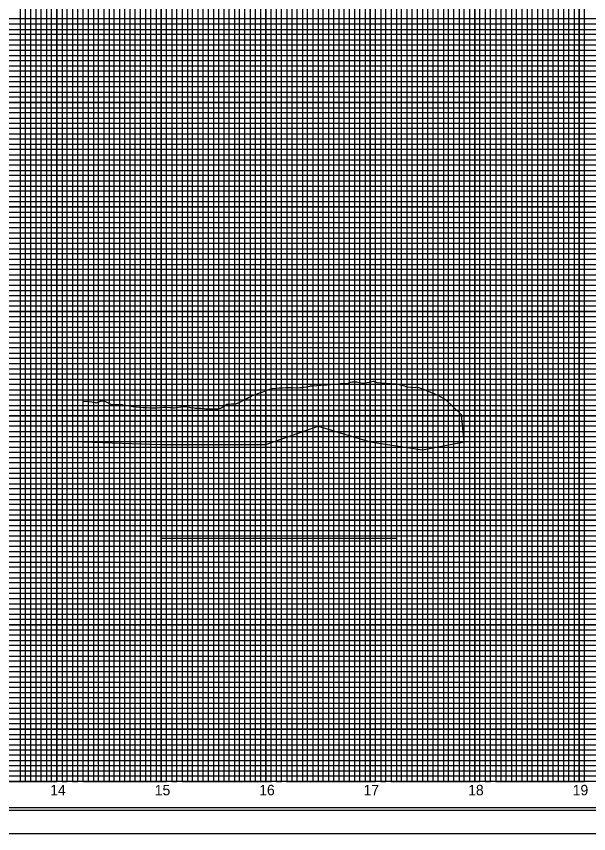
# Model space of a CAD drawing. Extents: x 1632447 to 1634147, y 883210 to 885181.
# Drawn here: x 1633075 to 1633623, y 883898 to 884680 of the extents above; entities that cross this region are included whole.
import ezdxf

# ---------------------------------------------------------------- set-up
doc = ezdxf.new("R2010")
doc.units = 0
for name, color, linetype in [('Exist Vertical Profile Horizontal Axis Label Major', 7, 'Continuous'), ('Prop CMT Undercut Boundary', 7, 'Continuous'), ('Prop VPI Label', 7, 'Continuous'), ('Scratch_Level_8', 7, 'Continuous'), ('Sheet Cutting Line CELL', 7, 'Continuous'), ('Sheet DOT Grid CELL', 7, 'Continuous'), ('Sheet Plot Border Inside CELL', 7, 'Continuous'), ('Sheet Plot Border Outside CELL', 7, 'Continuous'), ('Sheet Profile CELL', 7, 'Continuous'), ('Sheet Profile Grid Major CELL', 7, 'Continuous'), ('Sheet Profile Grid Middle CELL', 7, 'Continuous'), ('Sheet Profile Grid Minor CELL', 7, 'Continuous'), ('Stewart Plot Border Xerox6279 and LJ5000', 7, 'Continuous')]:
    doc.layers.add(name, color=color, linetype=linetype)

msp = doc.modelspace()

# ---------------------------------------------------------------- linework, layer by layer
at = {"layer": 'Prop CMT Undercut Boundary'}
for p, q in [((1633138.86, 884311.82), (1633138.86, 884272.61)), ((1633501.21, 884298.45), (1633485.73, 884313.21)), ((1633503.86, 884272.61), (1633501.21, 884298.45)), ((1633313.86, 884270.11), (1633363.86, 884287.61)), ((1633363.86, 884287.61), (1633413.86, 884272.61)), ((1633138.86, 884272.61), (1633213.86, 884270.11)), ((1633413.86, 884272.61), (1633463.86, 884265.11)), ((1633463.86, 884265.11), (1633503.86, 884272.61)), ((1633213.86, 884270.11), (1633313.86, 884270.11))]:
    msp.add_line(p, q, dxfattribs=at)
msp.add_lwpolyline([(1633138.86, 884311.82), (1633144.17, 884311.31), (1633147.43, 884310.96), (1633150.69, 884310.26), (1633151.68, 884310.05), (1633153.95, 884311.08), (1633156.17, 884312.08), (1633157.2, 884311.98), (1633159.45, 884311.77), (1633160.46, 884311.28), (1633163.72, 884309.68), (1633166.24, 884308.45), (1633166.98, 884308.44), (1633170.24, 884308.42), (1633173.5, 884308.39), (1633174.84, 884308.38), (1633176.31, 884308.37), (1633176.75, 884308.3), (1633180.01, 884307.76), (1633183.27, 884307.22), (1633186.53, 884306.71), (1633188.67, 884306.43), (1633189.79, 884306.33), (1633193.05, 884306.04), (1633196.41, 884305.74), (1633197.25, 884305.54), (1633199.56, 884305.51), (1633202.82, 884305.45), (1633206.08, 884305.4), (1633206.45, 884305.39), (1633208.29, 884305.36), (1633209.34, 884305.42), (1633212.6, 884305.64), (1633215.85, 884305.85), (1633216.49, 884305.89), (1633219.11, 884305.82), (1633222.37, 884305.72), (1633223.46, 884305.69), (1633225.63, 884305.35), (1633226.52, 884305.2), (1633228.89, 884305.63), (1633232.15, 884306.22), (1633232.82, 884306.35), (1633235.4, 884306.5), (1633236.54, 884306.56), (1633238.66, 884306.23), (1633240.77, 884305.9), (1633241.92, 884305.71), (1633245.18, 884305.15), (1633246.56, 884304.91), (1633248.44, 884304.9), (1633251.7, 884304.87), (1633254.95, 884304.58), (1633256.58, 884304.43), (1633258.21, 884304.43), (1633261.47, 884304.41), (1633261.94, 884304.41), (1633264.73, 884304.29), (1633266.59, 884304.22), (1633267.99, 884304.44), (1633270.85, 884304.9), (1633271.25, 884305.16), (1633274.5, 884307.32), (1633276.59, 884308.7), (1633277.76, 884308.81), (1633281.02, 884309.11), (1633281.97, 884309.19), (1633284.28, 884309.16), (1633285.04, 884309.15), (1633287.54, 884309.95), (1633287.92, 884310.07), (1633290.8, 884311.62), (1633294.05, 884313.36), (1633297.31, 884315.09), (1633300.19, 884316.53), (1633300.57, 884316.76), (1633300.99, 884317.01), (1633303.83, 884318.05), (1633307.09, 884319.25), (1633310.35, 884320.45), (1633313.6, 884321.64), (1633316.86, 884322.83), (1633320.12, 884323.94), (1633323.38, 884324.12), (1633326.64, 884324.3), (1633329.9, 884324.52), (1633333.15, 884324.63), (1633336.6, 884324.75), (1633339.67, 884324.64), (1633343.19, 884324.52), (1633346.19, 884324.78), (1633346.6, 884324.82), (1633349.45, 884324.92), (1633350.15, 884324.94), (1633352.7, 884325.49), (1633355.96, 884326.19), (1633356.61, 884326.33), (1633359.22, 884326.48), (1633362.75, 884326.68), (1633365.74, 884327.02), (1633366.61, 884327.13), (1633369, 884327.2), (1633372.43, 884327.32), (1633375.51, 884327.76), (1633376.62, 884327.92), (1633378.77, 884327.88), (1633382.04, 884327.83), (1633385.29, 884328.49), (1633386.63, 884328.76), (1633388.55, 884328.7), (1633391.8, 884328.69), (1633395.06, 884329.78), (1633396.64, 884330.31), (1633398.32, 884330.28), (1633401.08, 884330.23), (1633406.66, 884328.94), (1633412.9, 884329.75), (1633416.67, 884330.91), (1633420.04, 884329.7), (1633426.69, 884328.82), (1633429.51, 884328.98), (1633436.71, 884328.14), (1633438.99, 884328.21), (1633446.72, 884326.29), (1633448.47, 884325.44), (1633456.74, 884324.92), (1633457.94, 884325.49), (1633466.75, 884322.5), (1633467.68, 884321.95), (1633479.29, 884317.01), (1633485.73, 884313.21)], dxfattribs=at)
at = {"layer": 'Prop VPI Label'}
msp.add_lwpolyline([(1633213.86, 884180.5), (1633438.86, 884180.5), (1633438.86, 883997.61), (1633213.86, 883997.61)], close=True, dxfattribs=at)
at = {"layer": 'Scratch_Level_8'}
msp.add_lwpolyline([(1632663.86, 883947.61), (1632663.86, 885084.12), (1634063.86, 884811.56), (1634013.86, 884541.53), (1634013.86, 883947.61)], close=True, dxfattribs=at)
at = {"layer": 'Sheet Cutting Line CELL'}
msp.add_line((1632446.86, 883897.61), (1634130.86, 883897.61), dxfattribs=at)
at = {"layer": 'Sheet DOT Grid CELL'}
for p, q in [((1633113.86, 884972.61), (1633113.86, 883947.61)), ((1633163.86, 884972.61), (1633163.86, 883947.61)), ((1633213.86, 884972.61), (1633213.86, 883947.61)), ((1633263.86, 884972.61), (1633263.86, 883947.61)), ((1633313.86, 884972.61), (1633313.86, 883947.61)), ((1633363.86, 884972.61), (1633363.86, 883947.61)), ((1633413.86, 884972.61), (1633413.86, 883947.61)), ((1633463.86, 884972.61), (1633463.86, 883947.61)), ((1633513.86, 884972.61), (1633513.86, 883947.61)), ((1633563.86, 884972.61), (1633563.86, 883947.61)), ((1633613.86, 884972.61), (1633613.86, 883947.61)), ((1632613.86, 884647.61), (1634113.86, 884647.61)), ((1632613.86, 884597.61), (1634113.86, 884597.61)), ((1632613.86, 884547.61), (1634113.86, 884547.61)), ((1632613.86, 884497.61), (1634113.86, 884497.61)), ((1632613.86, 884447.61), (1634113.86, 884447.61)), ((1632613.86, 884397.61), (1634113.86, 884397.61)), ((1632613.86, 884347.61), (1634113.86, 884347.61)), ((1632613.86, 884297.61), (1634113.86, 884297.61)), ((1632613.86, 884247.61), (1634113.86, 884247.61)), ((1632613.86, 884197.61), (1634113.86, 884197.61)), ((1632613.86, 884147.61), (1634113.86, 884147.61)), ((1632613.86, 884097.61), (1634113.86, 884097.61)), ((1632613.86, 884047.61), (1634113.86, 884047.61)), ((1632613.86, 883997.61), (1634113.86, 883997.61))]:
    msp.add_line(p, q, dxfattribs=at)
at = {"layer": 'Sheet Plot Border Inside CELL'}
msp.add_lwpolyline([(1634126.36, 884975.16), (1632459.86, 884975.16), (1632459.86, 883920.06), (1634126.36, 883920.06)], close=True, dxfattribs=at)
at = {"layer": 'Sheet Plot Border Outside CELL'}
msp.add_lwpolyline([(1634130.86, 884997.61), (1632446.86, 884997.61), (1632446.86, 883897.61), (1634130.86, 883897.61)], close=True, dxfattribs=at)
at = {"layer": 'Sheet Profile CELL'}
msp.add_line((1634113.86, 883947.61), (1632613.86, 883947.61), dxfattribs=at)
msp.add_lwpolyline([(1634113.86, 884972.61), (1632613.86, 884972.61), (1632613.86, 883922.61), (1634113.86, 883922.61)], close=True, dxfattribs=at)
at = {"layer": 'Sheet Profile Grid Major CELL'}
for points in [[(1633063.86, 883947.61), (1633113.86, 883947.61), (1633113.86, 884972.61)], [(1633163.86, 884972.61), (1633163.86, 883947.61), (1633213.86, 883947.61), (1633213.86, 884972.61)], [(1633263.86, 884972.61), (1633263.86, 883947.61), (1633313.86, 883947.61), (1633313.86, 884972.61)], [(1633363.86, 884972.61), (1633363.86, 883947.61), (1633413.86, 883947.61), (1633413.86, 884972.61)], [(1633463.86, 884972.61), (1633463.86, 883947.61), (1633513.86, 883947.61), (1633513.86, 884972.61)], [(1633563.86, 884972.61), (1633563.86, 883947.61), (1633613.86, 883947.61), (1633613.86, 884972.61)], [(1634113.86, 884597.61), (1632613.86, 884597.61), (1632613.86, 884647.61), (1634113.86, 884647.61)], [(1634113.86, 884497.61), (1632613.86, 884497.61), (1632613.86, 884547.61), (1634113.86, 884547.61)], [(1634113.86, 884397.61), (1632613.86, 884397.61), (1632613.86, 884447.61), (1634113.86, 884447.61)], [(1634113.86, 884297.61), (1632613.86, 884297.61), (1632613.86, 884347.61), (1634113.86, 884347.61)], [(1634113.86, 884197.61), (1632613.86, 884197.61), (1632613.86, 884247.61), (1634113.86, 884247.61)], [(1634113.86, 884097.61), (1632613.86, 884097.61), (1632613.86, 884147.61), (1634113.86, 884147.61)], [(1634113.86, 883997.61), (1632613.86, 883997.61), (1632613.86, 884047.61), (1634113.86, 884047.61)]]:
    msp.add_lwpolyline(points, dxfattribs=at)
at = {"layer": 'Sheet Profile Grid Middle CELL'}
for points in [[(1633038.86, 883947.61), (1633088.86, 883947.61), (1633088.86, 884972.61)], [(1633138.86, 884972.61), (1633138.86, 883947.61), (1633188.86, 883947.61), (1633188.86, 884972.61)], [(1633238.86, 884972.61), (1633238.86, 883947.61), (1633288.86, 883947.61), (1633288.86, 884972.61)], [(1633338.86, 884972.61), (1633338.86, 883947.61), (1633388.86, 883947.61), (1633388.86, 884972.61)], [(1633438.86, 884972.61), (1633438.86, 883947.61), (1633488.86, 883947.61), (1633488.86, 884972.61)], [(1633538.86, 884972.61), (1633538.86, 883947.61), (1633588.86, 883947.61), (1633588.86, 884972.61)], [(1634113.86, 884672.61), (1632613.86, 884672.61), (1632613.86, 884622.61), (1634113.86, 884622.61)], [(1634113.86, 884572.61), (1632613.86, 884572.61), (1632613.86, 884522.61), (1634113.86, 884522.61)], [(1634113.86, 884472.61), (1632613.86, 884472.61), (1632613.86, 884422.61), (1634113.86, 884422.61)], [(1634113.86, 884372.61), (1632613.86, 884372.61), (1632613.86, 884322.61), (1634113.86, 884322.61)], [(1634113.86, 884272.61), (1632613.86, 884272.61), (1632613.86, 884222.61), (1634113.86, 884222.61)], [(1634113.86, 884172.61), (1632613.86, 884172.61), (1632613.86, 884122.61), (1634113.86, 884122.61)], [(1634113.86, 884072.61), (1632613.86, 884072.61), (1632613.86, 884022.61), (1634113.86, 884022.61)], [(1634113.86, 883972.61), (1632613.86, 883972.61)]]:
    msp.add_lwpolyline(points, dxfattribs=at)
at = {"layer": 'Sheet Profile Grid Minor CELL'}
for points in [[(1633073.86, 884972.61), (1633078.86, 884972.61), (1633078.86, 883947.61), (1633083.86, 883947.61), (1633083.86, 884972.61), (1633093.86, 884972.61), (1633093.86, 883947.61), (1633098.86, 883947.61), (1633098.86, 884972.61), (1633103.86, 884972.61), (1633103.86, 883947.61), (1633108.86, 883947.61), (1633108.86, 884972.61), (1633118.86, 884972.61), (1633118.86, 883947.61), (1633123.86, 883947.61), (1633123.86, 884972.61), (1633128.86, 884972.61), (1633128.86, 883947.61), (1633133.86, 883947.61), (1633133.86, 884972.61), (1633143.86, 884972.61), (1633143.86, 883947.61)], [(1633148.86, 884972.61), (1633148.86, 883947.61), (1633153.86, 883947.61), (1633153.86, 884972.61), (1633158.86, 884972.61), (1633158.86, 883947.61), (1633168.86, 883947.61), (1633168.86, 884972.61), (1633173.86, 884972.61), (1633173.86, 883947.61), (1633178.86, 883947.61), (1633178.86, 884972.61), (1633183.86, 884972.61), (1633183.86, 883947.61)], [(1633193.86, 883947.61), (1633193.86, 884972.61)], [(1633198.86, 884972.61), (1633198.86, 883947.61), (1633203.86, 883947.61), (1633203.86, 884972.61)], [(1633208.86, 884972.61), (1633208.86, 883947.61), (1633218.86, 883947.61), (1633218.86, 884972.61)], [(1633223.86, 884972.61), (1633223.86, 883947.61), (1633223.86, 883947.61), (1633228.86, 883947.61), (1633228.86, 884972.61)], [(1633233.86, 884972.61), (1633233.86, 883947.61), (1633243.86, 883947.61), (1633243.86, 884972.61)], [(1633248.86, 884972.61), (1633248.86, 883947.61), (1633253.86, 883947.61), (1633253.86, 884972.61)], [(1633258.86, 884972.61), (1633258.86, 883947.61), (1633268.86, 883947.61), (1633268.86, 884972.61)], [(1633273.86, 884972.61), (1633273.86, 883947.61), (1633278.86, 883947.61), (1633278.86, 884972.61)], [(1633283.86, 884972.61), (1633283.86, 883947.61), (1633293.86, 883947.61), (1633293.86, 884972.61)], [(1633298.86, 884972.61), (1633298.86, 883947.61), (1633303.86, 883947.61), (1633303.86, 884972.61)], [(1633308.86, 884972.61), (1633308.86, 883947.61), (1633318.86, 883947.61), (1633318.86, 884972.61)], [(1633323.86, 884972.61), (1633323.86, 883947.61), (1633328.86, 883947.61), (1633328.86, 884972.61)], [(1633333.86, 884972.61), (1633333.86, 883947.61), (1633343.86, 883947.61), (1633343.86, 884972.61)], [(1633348.86, 884972.61), (1633348.86, 883947.61), (1633353.86, 883947.61), (1633353.86, 884972.61)], [(1633358.86, 884972.61), (1633358.86, 883947.61), (1633368.86, 883947.61), (1633368.86, 884972.61)], [(1633373.86, 884972.61), (1633373.86, 883947.61)], [(1633373.86, 883947.61), (1633378.86, 883947.61), (1633378.86, 884972.01)], [(1633383.86, 884972.01), (1633383.86, 883947.61), (1633393.86, 883947.61), (1633393.86, 884972.61)], [(1633398.86, 884972.61), (1633398.86, 883947.61), (1633403.86, 883947.61), (1633403.86, 884972.61)], [(1633408.86, 884972.61), (1633408.86, 883947.61), (1633418.86, 883947.61), (1633418.86, 884972.61)], [(1633423.86, 884972.61), (1633423.86, 883947.61), (1633428.86, 883947.61), (1633428.86, 884972.61)], [(1633433.86, 884972.61), (1633433.86, 883947.61), (1633443.86, 883947.61), (1633443.86, 884972.61)], [(1633448.86, 884972.61), (1633448.86, 883947.61), (1633453.86, 883947.61), (1633453.86, 884972.61)], [(1633458.86, 884972.61), (1633458.86, 883947.61), (1633468.86, 883947.61), (1633468.86, 884972.61)], [(1633473.86, 884972.61), (1633473.86, 883947.61), (1633478.86, 883947.61), (1633478.86, 884972.61)], [(1633483.86, 884972.61), (1633483.86, 883947.61), (1633493.86, 883947.61), (1633493.86, 884972.61)], [(1633498.86, 884972.61), (1633498.86, 883947.61), (1633503.86, 883947.61), (1633503.86, 884972.61)], [(1633508.86, 884972.61), (1633508.86, 883947.61), (1633518.86, 883947.61), (1633518.86, 884972.61)], [(1633523.86, 884972.61), (1633523.86, 883947.61), (1633528.86, 883947.61), (1633528.86, 884972.61)], [(1633533.86, 884972.61), (1633533.86, 883947.61), (1633543.86, 883947.61), (1633543.86, 884972.61)], [(1633548.86, 884972.61), (1633548.86, 883947.61), (1633553.86, 883947.61), (1633553.86, 884972.61)], [(1633558.86, 884972.61), (1633558.86, 883947.61), (1633568.86, 883947.61), (1633568.86, 884972.61)], [(1633573.86, 884972.61), (1633573.86, 883947.61), (1633578.86, 883947.61), (1633578.86, 884972.61)], [(1633583.86, 884972.61), (1633583.86, 883947.61), (1633593.86, 883947.61), (1633593.86, 884972.61)], [(1633598.86, 884972.61), (1633598.86, 883947.61), (1633603.86, 883947.61), (1633603.86, 884972.61)], [(1633608.86, 884972.61), (1633608.86, 883947.61), (1633618.86, 883947.61), (1633618.86, 884972.61)], [(1634063.86, 884677.61), (1632663.86, 884677.61), (1632663.86, 884667.61), (1634063.86, 884667.61)], [(1634063.86, 884662.61), (1632663.86, 884662.61), (1632663.86, 884657.61), (1634063.86, 884657.61)], [(1634063.86, 884652.61), (1632663.86, 884652.61), (1632663.86, 884642.61), (1634063.86, 884642.61)], [(1634063.86, 884637.61), (1632663.86, 884637.61), (1632663.86, 884632.61), (1634063.86, 884632.61)], [(1634063.86, 884627.61), (1632663.86, 884627.61), (1632663.86, 884617.61), (1634063.86, 884617.61)], [(1634063.86, 884612.61), (1632663.86, 884612.61), (1632663.86, 884607.61), (1634063.86, 884607.61)], [(1634063.86, 884602.61), (1632663.86, 884602.61), (1632663.86, 884592.61), (1634063.86, 884592.61)], [(1634063.86, 884587.61), (1632663.86, 884587.61), (1632663.86, 884582.61), (1634063.86, 884582.61)], [(1634063.86, 884577.61), (1632663.86, 884577.61), (1632663.86, 884567.61), (1634063.86, 884567.61)], [(1634063.86, 884562.61), (1632663.86, 884562.61), (1632663.86, 884557.61), (1634063.86, 884557.61)], [(1634063.86, 884552.61), (1632663.86, 884552.61), (1632663.86, 884542.61), (1634063.86, 884542.61)], [(1634063.86, 884537.61), (1632663.86, 884537.61), (1632663.86, 884532.61), (1634063.86, 884532.61)], [(1634063.86, 884527.61), (1632663.86, 884527.61), (1632663.86, 884517.61), (1634063.86, 884517.61)], [(1634063.86, 884512.61), (1632663.86, 884512.61), (1632663.86, 884507.61), (1634063.86, 884507.61)], [(1634063.86, 884502.61), (1632663.86, 884502.61), (1632663.86, 884492.61), (1634063.86, 884492.61)], [(1634063.86, 884487.61), (1632663.86, 884487.61), (1632663.86, 884482.61), (1634063.86, 884482.61)], [(1634063.86, 884477.61), (1632663.86, 884477.61), (1632663.86, 884467.61), (1634063.86, 884467.61)], [(1634063.86, 884462.61), (1632663.86, 884462.61), (1632663.86, 884457.61), (1634063.86, 884457.61)], [(1634063.86, 884452.61), (1632663.86, 884452.61)], [(1632663.86, 884442.61), (1634063.86, 884442.61)], [(1634063.86, 884437.61), (1632663.86, 884437.61), (1632663.86, 884432.61), (1634063.86, 884432.61)], [(1634063.86, 884427.61), (1632663.86, 884427.61), (1632663.86, 884417.61), (1634063.86, 884417.61)], [(1634063.86, 884412.61), (1632663.86, 884412.61), (1632663.86, 884407.61), (1634063.86, 884407.61)], [(1634063.86, 884402.61), (1632663.86, 884402.61), (1632663.86, 884392.61), (1634063.86, 884392.61)], [(1634063.86, 884387.61), (1632663.86, 884387.61), (1632663.86, 884382.61), (1634063.86, 884382.61)], [(1634063.86, 884377.61), (1632663.86, 884377.61), (1632663.86, 884367.61), (1634063.86, 884367.61)], [(1634063.86, 884362.61), (1632663.86, 884362.61), (1632663.86, 884357.61), (1634063.86, 884357.61)], [(1634063.86, 884352.61), (1632663.86, 884352.61), (1632663.86, 884342.61), (1634063.86, 884342.61)], [(1634063.86, 884337.61), (1632663.86, 884337.61), (1632663.86, 884332.61), (1634063.86, 884332.61)], [(1634063.86, 884327.61), (1632663.86, 884327.61), (1632663.86, 884317.61), (1634063.86, 884317.61)], [(1634063.86, 884312.61), (1632663.86, 884312.61), (1632663.86, 884307.61), (1634063.86, 884307.61)], [(1634063.86, 884302.61), (1632663.86, 884302.61), (1632663.86, 884292.61), (1634063.86, 884292.61)], [(1634063.86, 884287.61), (1632663.86, 884287.61), (1632663.86, 884282.61), (1634063.86, 884282.61)], [(1634063.86, 884277.61), (1632663.86, 884277.61), (1632663.86, 884267.61), (1634063.86, 884267.61)], [(1634063.86, 884262.61), (1632663.86, 884262.61), (1632663.86, 884257.61), (1634063.86, 884257.61)], [(1634063.86, 884252.61), (1632663.86, 884252.61), (1632663.86, 884242.61), (1634063.86, 884242.61)], [(1634063.86, 884237.61), (1632663.86, 884237.61), (1632663.86, 884232.61), (1634063.86, 884232.61)], [(1634063.86, 884227.61), (1632663.86, 884227.61), (1632663.86, 884217.61), (1634063.86, 884217.61)], [(1634063.86, 884212.61), (1632663.86, 884212.61), (1632663.86, 884207.61), (1634063.86, 884207.61)], [(1634063.86, 884202.61), (1632663.86, 884202.61), (1632663.86, 884192.61), (1634063.86, 884192.61)], [(1634063.86, 884187.61), (1632663.86, 884187.61), (1632663.86, 884182.61), (1634063.86, 884182.61)], [(1634063.86, 884177.61), (1632663.86, 884177.61), (1632663.86, 884167.61), (1634063.86, 884167.61)], [(1634063.86, 884162.61), (1632663.86, 884162.61), (1632663.86, 884157.61), (1634063.86, 884157.61)], [(1634063.86, 884152.61), (1632663.86, 884152.61)], [(1632663.86, 884142.61), (1634063.86, 884142.61)], [(1634063.86, 884137.61), (1632663.86, 884137.61), (1632663.86, 884132.61), (1634063.86, 884132.61)], [(1634063.86, 884127.61), (1632663.86, 884127.61)], [(1632663.86, 884117.61), (1634063.86, 884117.61)], [(1634063.86, 884112.61), (1632663.86, 884112.61), (1632663.86, 884107.61), (1634063.86, 884107.61)], [(1634063.86, 884102.61), (1632663.86, 884102.61), (1632663.86, 884092.61), (1634063.86, 884092.61)], [(1634063.86, 884087.61), (1632663.86, 884087.61), (1632663.86, 884082.61), (1634063.86, 884082.61)], [(1634063.86, 884077.61), (1632663.86, 884077.61), (1632663.86, 884067.61), (1634063.86, 884067.61)], [(1634063.86, 884062.61), (1632663.86, 884062.61), (1632663.86, 884057.61), (1634063.86, 884057.61)], [(1634063.86, 884052.61), (1632663.86, 884052.61), (1632663.86, 884042.61), (1634063.86, 884042.61)], [(1634063.86, 884037.61), (1632663.86, 884037.61), (1632663.86, 884032.61), (1634063.86, 884032.61)], [(1634063.86, 884027.61), (1632663.86, 884027.61), (1632663.86, 884017.61), (1634063.86, 884017.61)], [(1634063.86, 884012.61), (1632663.86, 884012.61), (1632663.86, 884007.61), (1634063.86, 884007.61)], [(1634063.86, 884002.61), (1632663.86, 884002.61), (1632663.86, 883992.61), (1634063.86, 883992.61)], [(1634063.86, 883987.61), (1632663.86, 883987.61), (1632663.86, 883982.61), (1634063.86, 883982.61)], [(1634063.86, 883977.61), (1632663.86, 883977.61), (1632663.86, 883967.61), (1634063.86, 883967.61)], [(1634063.86, 883962.61), (1632663.86, 883962.61), (1632663.86, 883957.61), (1634063.86, 883957.61)], [(1634063.86, 883952.61), (1632663.86, 883952.61)]]:
    msp.add_lwpolyline(points, dxfattribs=at)
at = {"layer": 'Stewart Plot Border Xerox6279 and LJ5000'}
msp.add_lwpolyline([(1632446.86, 883897.61), (1634146.86, 883897.61), (1634146.86, 884997.61), (1632446.86, 884997.61)], close=True, dxfattribs=at)

# ---------------------------------------------------------------- texts
at = {"layer": 'Exist Vertical Profile Horizontal Axis Label Major'}
for s, p in [('14', (1633107.51, 883934.32)), ('15', (1633207.6, 883934.32)), ('16', (1633307.55, 883934.32)), ('17', (1633407.4, 883934.32)), ('18', (1633507.53, 883934.32)), ('19', (1633607.57, 883934.32))]:
    msp.add_text(s, height=10, dxfattribs=at).set_placement(p)

doc.saveas('drawing.dxf')
